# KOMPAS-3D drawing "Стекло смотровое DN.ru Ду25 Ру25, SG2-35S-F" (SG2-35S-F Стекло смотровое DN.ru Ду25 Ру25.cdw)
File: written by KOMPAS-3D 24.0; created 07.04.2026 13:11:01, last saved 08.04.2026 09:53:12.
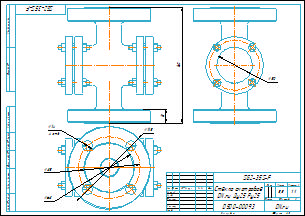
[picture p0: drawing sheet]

Document properties: Автор: Main; Форматы листов документа: A3; Полное имя файла: SG2-35S-F Стекло смотровое DN.ru Ду25 Ру25.m3d; Масса: 5.5; Наименование: Стекло смотровое DN.ru Ду25 Ру25; Количество листов документа: 1; Примечание: D500-00093

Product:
- Body: Тело 1  | qty 1
    Масса: 4.394636
- Part/product: Стекло смотровое DN.ru Ду25 Ру25  | designation SG2-35S-F
    Масса: 5.5
    Раздел спецификации: Прочие изделия
    Примечание: D500-00093

Views: Вид 1, Снизу, Проекционный вид 2
Referenced files in D:\DN.ru Аутсерс\Стекло смотровое DN.ru\Стекло смотровое DN.ru SG2-34G-F тип В ГОСТ 21836-2021 Ду100 Ру16, углеродистая сталь, фланцевое\: SG2-34G-F тип В Стекло смотровое DN.ru Ду100 Ру16.m3d, SG2-34G-F тип ВСтекло смотровое DN.ru Ду100 Ру16.cdw
Referenced files in D:\DN.ru Аутсерс\Стекло смотровое DN.ru\SG2-35S-F Стекло смотровое DN.ru Ду25 Ру25\: SG2-35S-F Стекло смотровое DN.ru Ду25 Ру25.m3d
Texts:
  SG2-35S-F
  Стекло смотровое
  DN.ru Ду25 Ру25
  Стекло смотровое DN.ru Ду25 Ру25
  SG2-35S-F Стекло смотровое DN.ru Ду25 Ру25
Dimensions and other numbers on the sheet: 0; 3; 2; 4; 160; 18; 14; 4 отв.; 85; 115; 68; 1:1; 1; 5,5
